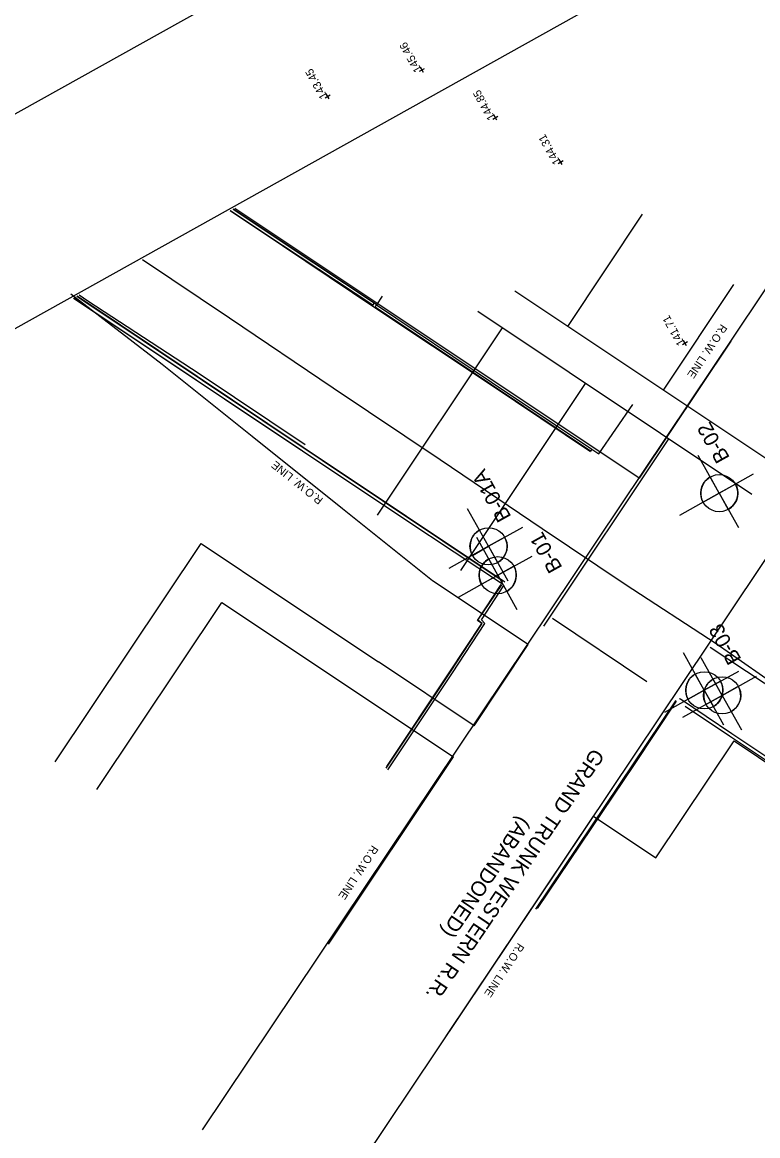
# Model space of a CAD drawing. Extents: x 13482447 to 13495412, y 324533 to 340229.
# Drawn here: x 13493140.7 to 13493376, y 331799.7 to 332156 of the extents above; entities that cross this region are included whole.
import ezdxf

# ---------------------------------------------------------------- set-up
doc = ezdxf.new("R2010")
doc.units = 0
for name, color, linetype in [('DETAIL_TEXT_DIMEN_PR', 7, 'Continuous'), ('Level 1', 7, 'Continuous'), ('TYPICAL_TEXT_DIMEN_PR', 7, 'Continuous'), ('V-ANNO-TEXT', 7, 'Continuous'), ('V-BLDG-OTLN', 7, 'Continuous'), ('V-PROP-LINE', 7, 'Continuous'), ('V-PROP-RWAY', 7, 'Continuous'), ('V-PROP-RWAY-IDEN', 7, 'Continuous'), ('V-PVMT-CNTR', 7, 'Continuous'), ('V-PVMT-ROAD', 7, 'Continuous'), ('V-SITE-FENC-DEMO', 7, 'Continuous'), ('V-SITE-WALK-DEMO', 7, 'Continuous'), ('V-STRC-OTLN', 7, 'Continuous'), ('V-STRC-WALL', 7, 'Continuous'), ('V-TOPO-DRAN-SPOT', 7, 'Continuous')]:
    doc.layers.add(name, color=color, linetype=linetype)

msp = doc.modelspace()

# ---------------------------------------------------------------- linework, layer by layer
at = {"layer": 'Level 1'}
for p, q in [((13493730.57, 332457.1), (13492930.67, 332010.77)), ((13493724.88, 332385.22), (13492994.84, 331977.87))]:
    msp.add_line(p, q, dxfattribs=at)
at = {"layer": 'TYPICAL_TEXT_DIMEN_PR'}
for p, q in [((13493363.72, 332005.33), (13493357.01, 332017.35)), ((13493363.72, 332005.33), (13493374.73, 332011.47)), ((13493363.72, 332005.33), (13493351.01, 331998.23)), ((13493363.72, 332005.33), (13493369.86, 331994.32)), ((13493289.9, 331988.33), (13493283.19, 332000.35)), ((13493289.9, 331988.33), (13493300.91, 331994.47)), ((13493292.84, 331979.08), (13493286.13, 331991.11)), ((13493289.9, 331988.33), (13493277.18, 331981.23)), ((13493289.9, 331988.33), (13493296.04, 331977.32)), ((13493292.84, 331979.08), (13493303.85, 331985.22)), ((13493292.84, 331979.08), (13493280.13, 331971.99)), ((13493292.84, 331979.08), (13493298.98, 331968.07)), ((13493358.94, 331942.25), (13493352.23, 331954.28)), ((13493364.66, 331940.63), (13493357.95, 331952.66)), ((13493358.94, 331942.25), (13493369.95, 331948.4)), ((13493364.66, 331940.63), (13493375.67, 331946.78)), ((13493358.94, 331942.25), (13493346.22, 331935.16)), ((13493364.66, 331940.63), (13493351.94, 331933.54)), ((13493358.94, 331942.25), (13493365.08, 331931.24)), ((13493364.66, 331940.63), (13493370.8, 331929.62))]:
    msp.add_line(p, q, dxfattribs=at)
for points in [[(13493358.53, 332002.43), (13493363.72, 332005.33), (13493360.83, 332010.52)], [(13493368.91, 332008.22), (13493363.72, 332005.33), (13493366.62, 332000.14)], [(13493284.71, 331985.43), (13493289.9, 331988.33), (13493287, 331993.52)], [(13493295.09, 331991.22), (13493289.9, 331988.33), (13493292.79, 331983.14)], [(13493287.65, 331976.18), (13493292.84, 331979.08), (13493289.94, 331984.27)], [(13493298.03, 331981.98), (13493292.84, 331979.08), (13493295.74, 331973.89)], [(13493353.75, 331939.36), (13493358.94, 331942.25), (13493356.04, 331947.44)], [(13493364.13, 331945.15), (13493358.94, 331942.25), (13493361.84, 331937.06)], [(13493359.47, 331937.74), (13493364.66, 331940.63), (13493361.76, 331945.82)], [(13493369.85, 331943.53), (13493364.66, 331940.63), (13493367.55, 331935.44)]]:
    msp.add_lwpolyline(points, dxfattribs=at)
for centre in [(13493363.72, 332005.33), (13493289.9, 331988.33), (13493292.84, 331979.08), (13493358.94, 331942.25), (13493364.66, 331940.63)]:
    msp.add_circle(centre, 5.94, dxfattribs=at)
for centre, start, end in [((13493363.72, 332005.33), 119.1605, 209.1605), ((13493363.72, 332005.33), 299.1605, 29.1605), ((13493289.9, 331988.33), 119.1605, 209.1605), ((13493289.9, 331988.33), 299.1605, 29.1605), ((13493292.84, 331979.08), 119.1605, 209.1605), ((13493292.84, 331979.08), 299.1605, 29.1605), ((13493358.94, 331942.25), 119.1605, 209.1605), ((13493364.66, 331940.63), 119.1605, 209.1605), ((13493358.94, 331942.25), 299.1605, 29.1605), ((13493364.66, 331940.63), 299.1605, 29.1605)]:
    msp.add_arc(centre, 5.94, start, end, dxfattribs=at)
at = {"layer": 'V-BLDG-OTLN'}
for points in [[(13493255.82, 332068.4), (13493253.99, 332065.59), (13493290.88, 332040.9), (13493322.93, 332019.39), (13493325.2, 332017.93), (13493336.08, 332033.66)], [(13493257.1, 331917.31), (13493277.69, 331948.2), (13493287.81, 331963.62), (13493286.51, 331964.68), (13493294.15, 331976)], [(13493257.66, 331916.81), (13493278.32, 331947.83), (13493288.67, 331963.62), (13493287.66, 331964.76), (13493294.8, 331975.74)], [(13493349.92, 331938.75), (13493349.7, 331938.89), (13493336.13, 331918.68), (13493304.95, 331872.24)], [(13493349.92, 331938.75), (13493336.54, 331918.46), (13493305.49, 331872.38)]]:
    msp.add_lwpolyline(points, dxfattribs=at)
at = {"layer": 'V-PROP-LINE'}
for p, q in [((13493315.22, 332058.69), (13493339.19, 332094.62)), ((13493345.83, 332038.26), (13493368.42, 332072.13)), ((13493380.86, 332014.89), (13493298.26, 332070)), ((13493374.2, 332004.91), (13493286.48, 332063.43)), ((13493254.38, 331998.29), (13493294.34, 332058.19)), ((13493281, 331980.53), (13493320.96, 332040.43)), ((13493307.62, 331962.77), (13493347.58, 332022.67)), ((13493360.87, 331956.1), (13493434.98, 331906.65))]:
    msp.add_line(p, q, dxfattribs=at)
at = {"layer": 'V-PROP-RWAY'}
for p, q in [((13493198.41, 331801.59), (13493450.97, 332178.76)), ((13493477.23, 332131.7), (13493224.66, 331754.53)), ((13493338.14, 332010.1), (13493208.69, 332096.46)), ((13493185.45, 332046.47), (13493156.22, 332068.96)), ((13493367.44, 332054.02), (13493338.14, 332010.1)), ((13493214.3, 332023.41), (13493185.45, 332046.47)), ((13493243.15, 332000.34), (13493214.3, 332023.41)), ((13493272, 331977.28), (13493243.15, 332000.34)), ((13493151.26, 331919.36), (13493197.88, 331989.23)), ((13493197.88, 331989.23), (13493224.08, 331971.75)), ((13493302.62, 331956.86), (13493272, 331977.28)), ((13493164.57, 331910.47), (13493204.53, 331970.37)), ((13493204.53, 331970.37), (13493278.64, 331920.92)), ((13493224.08, 331971.75), (13493254.69, 331951.33)), ((13493285.3, 331930.91), (13493302.62, 331956.86)), ((13493285.3, 331930.91), (13493254.69, 331951.33)), ((13493343.42, 331888.62), (13493368.47, 331926.05)), ((13493368.47, 331926.05), (13493463.54, 331862.41)), ((13493238.68, 331861.03), (13493278.64, 331920.92)), ((13493276.34, 331831.56), (13493323.48, 331901.97)), ((13493323.48, 331901.97), (13493343.42, 331888.62))]:
    msp.add_line(p, q, dxfattribs=at)
at = {"layer": 'V-PVMT-CNTR'}
msp.add_lwpolyline([(13493605.37, 331796), (13493578.55, 331813.26), (13493565.46, 331822.12), (13493559.01, 331826.3), (13493554.28, 331829.11), (13493520.81, 331851.15), (13493485.5, 331874.76), (13493449.91, 331898.35), (13493414.95, 331921.85), (13493381.07, 331944.31), (13493362.78, 331957.08), (13493333.61, 331976.1), (13493307.04, 331993.94), (13493274.45, 332015.96), (13493240.12, 332038.89), (13493207.02, 332061.34), (13493179.15, 332079.98)], dxfattribs=at)
at = {"layer": 'V-PVMT-ROAD'}
for points in [[(13493229.8, 332019.1), (13493224.06, 332022.94), (13493186.36, 332048.13), (13493157.08, 332067.66)], [(13493257.33, 331917.82), (13493277.47, 331948.19), (13493287.71, 331963.6), (13493286.4, 331964.63), (13493293.96, 331976.09), (13493293.96, 331976.09)]]:
    msp.add_lwpolyline(points, dxfattribs=at)
at = {"layer": 'V-SITE-FENC-DEMO'}
for points in [[(13493253.99, 332065.59), (13493208.21, 332096.19)], [(13493231.24, 332020.79), (13493197.27, 332043.51), (13493161.62, 332066.79), (13493158.86, 332068.66)], [(13493294.6, 331977.05), (13493159.77, 332067.17), (13493158.13, 332068.25)]]:
    msp.add_lwpolyline(points, dxfattribs=at)
at = {"layer": 'V-SITE-WALK-DEMO'}
msp.add_lwpolyline([(13493322.51, 332018.54), (13493290.45, 332040.06), (13493253.78, 332064.45), (13493223.94, 332084.47), (13493207.22, 332095.64)], dxfattribs=at)
at = {"layer": 'V-STRC-OTLN'}
msp.add_lwpolyline([(13493340.54, 331945), (13493310.4, 331965.25)], dxfattribs=at)
at = {"layer": 'V-STRC-WALL'}
for points in [[(13493252.82, 332065.44), (13493223.98, 332084.55), (13493207.32, 332095.69)], [(13493252.84, 332065.43), (13493253.3, 332066.1), (13493224.48, 332085.2), (13493208.14, 332096.15)], [(13493294.39, 331976.15), (13493294.34, 331976.18), (13493263.41, 331996.74), (13493230.36, 332018.8), (13493196.31, 332041.48), (13493159.44, 332066.16), (13493157.14, 332067.7)], [(13493295.06, 331976.87), (13493294.96, 331976.93), (13493263.59, 331997.86), (13493230.59, 332019.98), (13493196.66, 332042.63), (13493159.86, 332067.28), (13493158.28, 332068.33)], [(13493322.92, 332019.38), (13493322.48, 332018.82), (13493290.54, 332040.16), (13493253.65, 332064.81), (13493253.99, 332065.59)], [(13493530.31, 331818.51), (13493530.79, 331819.47), (13493507.77, 331834.83), (13493473.6, 331857.65), (13493438.19, 331881.24), (13493402.32, 331905.28), (13493367.72, 331928.34), (13493351.29, 331939.37), (13493351.03, 331939.54)], [(13493530.31, 331818.51), (13493507.15, 331834.06), (13493473.12, 331856.78), (13493437.57, 331880.51), (13493401.84, 331904.3), (13493367.03, 331927.53), (13493352.79, 331937.07)]]:
    msp.add_lwpolyline(points, dxfattribs=at)
at = {"layer": 'V-TOPO-DRAN-SPOT'}
for p, q in [((13493267.76, 332140.34), (13493269.38, 332141.25)), ((13493269.04, 332139.96), (13493268.1, 332141.63)), ((13493237.63, 332131.85), (13493239.25, 332132.76)), ((13493238.9, 332131.47), (13493237.97, 332133.15)), ((13493291.3, 332125.05), (13493292.92, 332125.95)), ((13493292.58, 332124.66), (13493291.64, 332126.34)), ((13493312.2, 332110.86), (13493313.82, 332111.77)), ((13493313.47, 332110.48), (13493312.54, 332112.15)), ((13493353.19, 332052.52), (13493352.26, 332054.2)), ((13493351.92, 332052.91), (13493353.54, 332053.81))]:
    msp.add_line(p, q, dxfattribs=at)

# ---------------------------------------------------------------- texts
at = {"layer": 'DETAIL_TEXT_DIMEN_PR'}
for s, p in [('B-02', (13493367.22, 332016.66)), ('B-01A', (13493297.28, 331997.8)), ('B-01', (13493313.63, 331981.51)), ('B-03', (13493370.93, 331952.18))]:
    msp.add_text(s, height=4.8, rotation=119.1605, dxfattribs=at).set_placement(p)
at = {"layer": 'V-ANNO-TEXT'}
for s, p in [('GRAND TRUNK WESTERN R.R.', (13493323.31, 331923.98)), ('(ABANDONED)', (13493299.83, 331902.26))]:
    msp.add_text(s, height=4.8, rotation=235.7802, dxfattribs=at).set_placement(p)
at = {"layer": 'V-PROP-RWAY-IDEN'}
for rotation, p in [(236.2892, (13493364.32, 332059.62)), (141.3566, (13493237.15, 332003.5)), (236.2892, (13493252.68, 331892.85)), (236.2892, (13493299.36, 331861.6))]:
    msp.add_text('R.O.W. LINE', height=2.56, rotation=rotation, dxfattribs=at).set_placement(p)
at = {"layer": 'V-TOPO-DRAN-SPOT'}
for s, p in [('145.46', (13493268.57, 332140.8)), ('143.45', (13493238.44, 332132.31)), ('144.85', (13493292.11, 332125.5)), ('144.31', (13493313.01, 332111.31)), ('141.71', (13493352.73, 332053.36))]:
    msp.add_text(s, height=2.56, rotation=119.1605, dxfattribs=at).set_placement(p)

doc.saveas('drawing.dxf')
